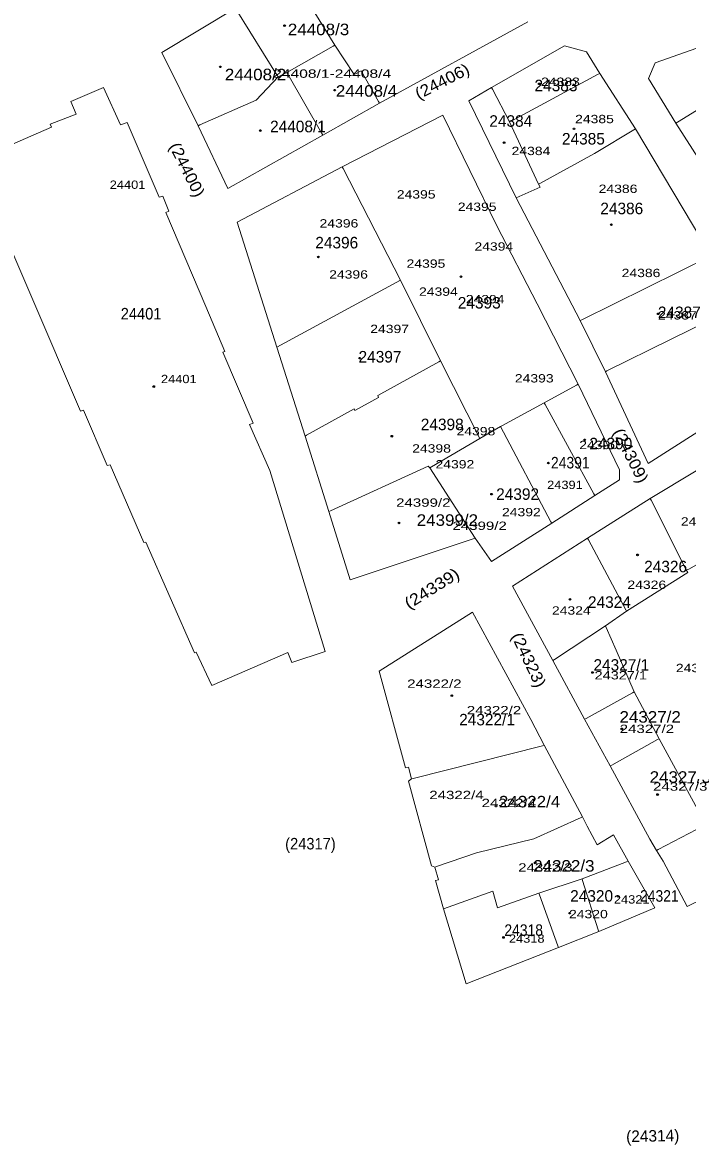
# Model space of a CAD drawing. Extents: x 649608 to 651081, y 237980 to 241202.
# Drawn here: x 650118.4 to 650325.9, y 238723.1 to 239073.7 of the extents above; entities that cross this region are included whole.
import ezdxf

# ---------------------------------------------------------------- set-up
doc = ezdxf.new("R2010")
doc.units = 0
doc.header["$PDMODE"] = 32
doc.header["$PDSIZE"] = 0.5
for name, color, linetype in [('19', 7, 'Continuous'), ('20', 7, 'Continuous'), ('6', 7, 'Continuous')]:
    doc.layers.add(name, color=color, linetype=linetype)
doc.layers.add('3', color=7, linetype='Continuous', lineweight=13)
doc.layers.add('5', color=7, linetype='Continuous', lineweight=13)

msp = doc.modelspace()

# ---------------------------------------------------------------- linework, layer by layer
at = {"layer": '3'}
msp.add_line((650333.268, 239000.784), (650309.651, 239040.458), dxfattribs=at)
for points in [[(650184.817, 239078.16), (650161.861, 239064.266), (650173.208, 239041.436)], [(650173.208, 239041.436), (650182.485, 239021.849), (650212.074, 239038.491), (650229.817, 239048.491), (650276.074, 239073.838)], [(650337.653, 239068.717), (650315.85, 239061.08), (650313.77, 239056.136), (650322.253, 239042.174), (650334.272, 239023.41), (650343.346, 239001.41), (650344.344, 239002.082)], [(650264.768, 239053.36), (650287.528, 239066.365), (650294.406, 239064.465), (650298.502, 239057.736), (650309.651, 239040.458)], [(650175.64, 238984.959), (650163.177, 239014.357), (650164.099, 239014.754), (650162.193, 239019.433), (650161.093, 239019.088), (650151.078, 239042.463), (650149.029, 239041.672), (650143.677, 239053.337), (650133.483, 239049.027), (650135.139, 239045.081), (650127.072, 239041.916), (650127.448, 239040.955), (650111.131, 239033.869), (650111.508, 239033.059), (650106.205, 239030.78), (650109.243, 239023.797), (650106.374, 239022.533), (650136.506, 238952.341)], [(650272.393, 239018.949), (650257.647, 239049.18), (650264.768, 239053.36)], [(650266.358, 239010.14), (650249.604, 239044.759), (650218.18, 239028.61)], [(650218.18, 239028.61), (650185.369, 239011.287), (650197.778, 238972.308)], [(650340.965, 238984.736), (650352.967, 238961.072), (650313.65, 238936.034), (650300.262, 238964.625), (650292.437, 238980.621), (650272.393, 239018.949)], [(650266.358, 239010.14), (650279.001, 238985.828), (650291.772, 238960.734)], [(650136.506, 238952.341), (650137.454, 238952.635), (650144.783, 238935.359), (650145.756, 238935.577), (650156.255, 238911.334), (650156.895, 238911.454), (650172.087, 238876.873), (650172.575, 238877.07), (650177.447, 238866.68), (650201.152, 238876.97), (650202.447, 238873.829), (650212.877, 238877.26), (650195.538, 238933.784), (650189.2, 238948.148), (650190.405, 238948.566), (650180.957, 238970.73), (650181.496, 238971.002), (650175.64, 238984.959)], [(650197.778, 238972.308), (650206.555, 238944.525), (650213.997, 238921.017)], [(650291.772, 238960.734), (650304.704, 238934.005), (650304.638, 238930.876), (650296.977, 238926.013), (650283.535, 238917.318)], [(650271.291, 238897.715), (650294.729, 238912.715), (650314.262, 238925.069), (650328.6, 238933.699), (650339.242, 238939.231)], [(650213.997, 238921.017), (650220.594, 238899.688), (650259.671, 238912.705)], [(650283.535, 238917.318), (650264.713, 238905.352), (650259.671, 238912.705)], [(650316.195, 238815.232), (650314.136, 238818.688), (650301.76, 238841.589), (650293.747, 238856.171), (650283.902, 238874.463), (650271.291, 238897.715)], [(650258.814, 238889.536), (650229.669, 238871.195), (650237.885, 238840.995), (650238.832, 238841.188), (650239.815, 238837.546)], [(650258.814, 238889.536), (650277.037, 238856.037), (650281.192, 238848.042), (650293.179, 238825.69)], [(650239.815, 238837.546), (650238.812, 238836.799), (650245.968, 238810.418), (650247.063, 238810.029)], [(650293.179, 238825.69), (650294.592, 238822.807), (650297.751, 238816.969), (650302.775, 238820.084), (650307.367, 238811.893)], [(650340.606, 238804.956), (650325.826, 238797.694), (650318.278, 238811.853), (650316.195, 238815.232)], [(650307.367, 238811.893), (650315.712, 238797.315), (650298.217, 238789.907), (650285.652, 238784.906), (650256.856, 238773.622)], [(650247.063, 238810.029), (650248.171, 238806.083), (650247.3, 238805.839), (650249.736, 238796.961), (650256.856, 238773.622)]]:
    msp.add_lwpolyline(points, dxfattribs=at)
at = {"layer": '5'}
for p, q in [((650261.075, 238943.801), (650248.799, 238968.003)), ((650261.075, 238943.801), (650267.497, 238947.489)), ((650259.671, 238912.705), (650245.476, 238934.688))]:
    msp.add_line(p, q, dxfattribs=at)
for points in [[(650215.882, 239066.55), (650202.541, 239088.167), (650202.232, 239088.667)], [(650184.817, 239078.16), (650185.127, 239077.66), (650197.855, 239057.151), (650198.165, 239056.651)], [(650200.932, 239057.991), (650215.382, 239066.264), (650215.882, 239066.55)], [(650229.817, 239048.491), (650229.533, 239048.991), (650224.121, 239058.519), (650221.917, 239057.402), (650215.882, 239066.55)], [(650173.208, 239041.436), (650173.708, 239041.656), (650191.319, 239049.416), (650198.165, 239056.651), (650200.932, 239057.991)], [(650212.074, 239038.491), (650211.788, 239038.991), (650201.218, 239057.491), (650200.932, 239057.991)], [(650270.356, 239042.622), (650270.856, 239042.89), (650298.002, 239057.468), (650298.502, 239057.736)], [(650270.356, 239042.622), (650265.028, 239052.86), (650264.768, 239053.36)], [(650322.253, 239042.174), (650322.753, 239042.485), (650330.07, 239047.034), (650333.777, 239040.91), (650340.098, 239044.215), (650347.89, 239047.982), (650346.82, 239050.69)], [(650272.393, 239018.949), (650279.87, 239022.227), (650279.364, 239023.158), (650270.356, 239042.622)], [(650279.364, 239023.158), (650279.864, 239023.432), (650296.858, 239032.734), (650309.651, 239040.458)], [(650218.18, 239028.61), (650218.44, 239028.11), (650236.329, 238993.201)], [(650292.437, 238980.621), (650292.937, 238980.868), (650333.268, 239000.784)], [(650248.799, 238968.003), (650236.329, 238993.201), (650197.778, 238972.308)], [(650300.262, 238964.625), (650300.762, 238964.872), (650340.465, 238984.489), (650340.965, 238984.736)], [(650248.799, 238968.003), (650248.299, 238967.728), (650229.269, 238957.261), (650229.432, 238956.57), (650222.113, 238952.573), (650221.845, 238953.088), (650207.055, 238944.805), (650206.555, 238944.525)], [(650281.184, 238954.926), (650291.272, 238960.46), (650291.772, 238960.734)], [(650267.497, 238947.489), (650267.997, 238947.761), (650281.184, 238954.926)], [(650281.184, 238954.926), (650281.457, 238954.426), (650296.704, 238926.513), (650296.977, 238926.013)], [(650267.497, 238947.489), (650283.269, 238917.818), (650283.535, 238917.318)], [(650261.075, 238943.801), (650245.976, 238934.98), (650245.476, 238934.688)], [(650245.476, 238934.688), (650244.97, 238935.173), (650214.497, 238921.246), (650213.997, 238921.017)], [(650314.262, 238925.069), (650314.512, 238924.569), (650325.431, 238902.757)], [(650294.729, 238912.715), (650294.995, 238912.215), (650306.609, 238890.361), (650306.875, 238889.861)], [(650306.875, 238889.861), (650325.951, 238901.956), (650325.431, 238902.757), (650326.272, 238902.97), (650338.939, 238910.192)], [(650283.902, 238874.463), (650284.402, 238874.795), (650300.258, 238885.338), (650306.875, 238889.861)], [(650300.258, 238885.338), (650300.479, 238884.838), (650303.643, 238877.687), (650309.235, 238864.715), (650317.019, 238850.08), (650331.613, 238823.271)], [(650293.747, 238856.171), (650294.247, 238856.447), (650308.735, 238864.439), (650309.235, 238864.715)], [(650301.76, 238841.589), (650302.26, 238841.867), (650316.519, 238849.802), (650317.019, 238850.08)], [(650281.192, 238848.042), (650280.692, 238847.915), (650240.315, 238837.673), (650239.815, 238837.546)], [(650293.179, 238825.69), (650292.679, 238825.463), (650277.952, 238818.789), (650260.013, 238814.478)], [(650316.195, 238815.232), (650316.695, 238815.493), (650331.113, 238823.01), (650331.613, 238823.271)], [(650260.013, 238814.478), (650247.563, 238810.201), (650247.063, 238810.029)], [(650293.019, 238806.365), (650306.867, 238811.7), (650307.367, 238811.893)], [(650249.736, 238796.961), (650265.134, 238802.484), (650266.575, 238797.255), (650279.553, 238801.908), (650293.019, 238806.365)], [(650298.217, 238789.907), (650298.059, 238790.407), (650293.177, 238805.865), (650293.019, 238806.365)], [(650285.652, 238784.906), (650285.473, 238785.406), (650279.732, 238801.408), (650279.553, 238801.908)]]:
    msp.add_lwpolyline(points, dxfattribs=at)
at = {"layer": '6'}
for p in [(650200.171, 239072.659), (650180.147, 239059.798), (650279.607, 239054.493), (650215.793, 239052.52), (650192.592, 239039.92), (650290.498, 239040.447), (650268.675, 239036.154), (650302.126, 239010.539), (650210.713, 239000.459), (650255.191, 238994.28), (650316.754, 238982.704), (650223.62, 238968.863), (650159.371, 238960.008), (650233.638, 238944.51), (650293.833, 238943.373), (650282.497, 238936.122), (650264.756, 238926.42), (650235.863, 238917.43), (650310.297, 238907.465), (650289.211, 238893.589), (650296.265, 238870.754), (650252.353, 238863.541), (650305.396, 238853.152), (650316.546, 238832.656), (650266.152, 238829.035), (650278.364, 238811.325), (650304.202, 238800.9), (650289.106, 238795.635), (650268.488, 238788.053)]:
    msp.add_point(p, dxfattribs=at)

# ---------------------------------------------------------------- texts
at = {"layer": '19'}
for s, width, p in [('24408/3', 1.1, (650201.211, 239069.683)), ('24408/2', 1.1, (650181.546, 239055.605)), ('24408/4', 1.1, (650216.174, 239050.486)), ('24401', 0.95, (650149.055, 238980.948)), ('24391', 0.9, (650283.293, 238934.449)), ('24399/2', 1.1, (650241.396, 238916.531)), ('24327/2', 1.1, (650304.668, 238855.099)), ('24327/3', 1.1, (650314.073, 238836.328)), ('24322/4', 1.1, (650267.047, 238828.649)), ('(24317)', 0.95, (650200.362, 238815.525)), ('24322/3', 1.1, (650277.736, 238808.598)), ('24321', 0.9, (650311.081, 238799.213)), ('24318', 0.9, (650268.757, 238788.548))]:
    msp.add_text(s, height=3.6, dxfattribs=dict(at, width=width)).set_placement(p)
for s, rotation, width, p in [('(24406)', 27.167, 1.1, (650242.04, 239049.524)), ('(24400)', 296.776, 1.1, (650164.052, 239035.056)), ('(24309)', 296.611, 1.1, (650302.489, 238945.823)), ('(24339)', 32.182, 1.15, (650238.994, 238890.404)), ('(24323)', 295.56, 1.1, (650270.791, 238882.154))]:
    msp.add_text(s, height=3.6, rotation=rotation, dxfattribs=dict(at, width=width)).set_placement(p)
for s, p in [('24383', (650278.163, 239052.191)), ('24408/1', (650195.654, 239039.394)), ('24384', (650264.055, 239041.1)), ('24385', (650286.713, 239035.554)), ('24386', (650298.685, 239013.797)), ('24396', (650209.761, 239003.132)), ('24393', (650254.223, 238984.361)), ('24387', (650316.64, 238981.374)), ('24397', (650223.259, 238967.517)), ('24398', (650242.68, 238946.393)), ('24390', (650295.263, 238940.421)), ('24392', (650266.193, 238924.637)), ('24326', (650312.364, 238902.026)), ('24324', (650294.836, 238890.934)), ('24327/1', (650296.545, 238871.31)), ('24322/1', (650254.65, 238854.245)), ('24320', (650289.278, 238799.213))]:
    msp.add_text(s, height=3.6, dxfattribs=at).set_placement(p)
msp.add_text('(24314)', height=3.6, rotation=1.155, dxfattribs=at).set_placement((650306.776, 238724.162))
at = {"layer": '20'}
for s, width, p in [('24408/1-24408/4', 1.4, (650196.62, 239056.393)), ('24383', 1.25, (650280.203, 239053.856)), ('24385', 1.25, (650290.821, 239042.216)), ('24384', 1.25, (650271.006, 239032.253)), ('24401', 1.15, (650145.631, 239021.713)), ('24386', 1.25, (650298.171, 239020.444)), ('24395', 1.25, (650235.196, 239018.697)), ('24395', 1.25, (650254.224, 239014.831)), ('24396', 1.25, (650211.097, 239009.65)), ('24394', 1.25, (650259.422, 239002.428)), ('24395', 1.25, (650238.242, 238997.089)), ('24396', 1.25, (650214.095, 238993.705)), ('24386', 1.25, (650305.344, 238994.169)), ('24394', 1.25, (650242.135, 238988.341)), ('24394', 1.25, (650256.721, 238985.997)), ('24387', 1.25, (650316.692, 238980.939)), ('24397', 1.25, (650226.908, 238976.704)), ('24401', 1.15, (650161.622, 238961.067)), ('24393', 1.25, (650272.026, 238961.285)), ('24398', 1.25, (650253.832, 238944.785)), ('24398', 1.25, (650239.989, 238939.4)), ('24390', 1.25, (650292.121, 238940.492)), ('24392', 1.25, (650247.274, 238934.46)), ('24391', 1.15, (650282.094, 238928.022)), ('24399/2', 1.35, (650234.975, 238922.493)), ('24392', 1.25, (650268.011, 238919.517)), ('24399/2', 1.35, (650252.549, 238915.259)), ('24335', 1.25, (650323.827, 238916.61)), ('24326', 1.25, (650307.147, 238896.847)), ('24324', 1.25, (650283.59, 238888.821)), ('24327/1', 1.3, (650296.901, 238868.597)), ('24328', 1.25, (650322.262, 238870.863)), ('24322/2', 1.35, (650238.436, 238865.98)), ('24322/2', 1.35, (650257.03, 238857.692)), ('24327/2', 1.35, (650304.732, 238851.872)), ('24327/3', 1.35, (650315.131, 238833.86)), ('24322/4', 1.35, (650245.327, 238831.234)), ('24322/4', 1.35, (650261.655, 238828.734)), ('24322/3', 1.35, (650273.06, 238808.606)), ('24321', 1.15, (650302.928, 238798.631)), ('24320', 1.25, (650288.926, 238794.046)), ('24318', 1.15, (650270.167, 238786.404))]:
    msp.add_text(s, height=2.6, dxfattribs=dict(at, width=width)).set_placement(p)

doc.saveas('drawing.dxf')
